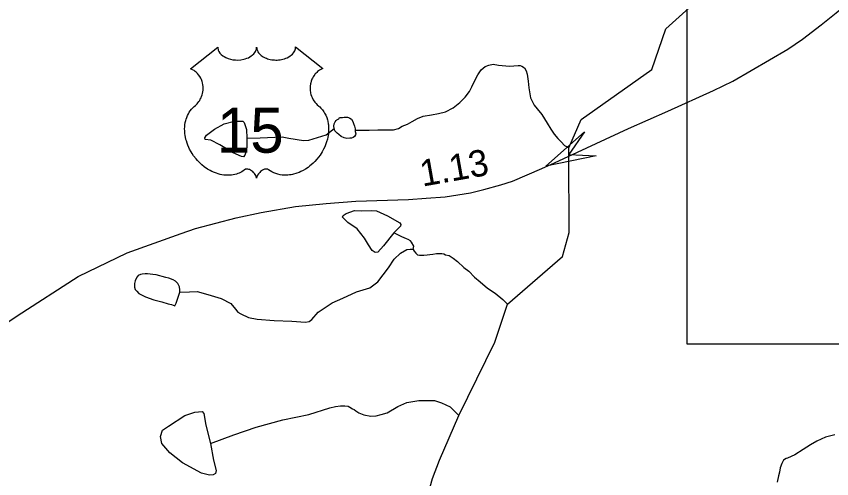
# Model space of a CAD drawing. Extents: x 2056842 to 2160602, y 826753 to 1016856.
# Drawn here: x 2083491 to 2087342, y 858683 to 860868 of the extents above; entities that cross this region are included whole.
import ezdxf

# ---------------------------------------------------------------- set-up
doc = ezdxf.new("R2010")
doc.units = 0
for name, color, linetype in [('Exist Hydrographic Creek Single Shore', 7, 'Continuous'), ('Exist Hydrographic Misc Water Feature', 7, 'Continuous'), ('Exist Road Primary US Attributed', 7, 'Continuous'), ('Exist Road Primary US Mileage Hundredths English Label', 7, 'Continuous'), ('Exist Road Primary US Shield CELL', 7, 'Continuous'), ('Exist Road Primary US Shield Number Label', 7, 'Continuous'), ('Exist Road Secondary Structure Standard Bridge Attributed CELL', 7, 'Continuous'), ('Scratch_Level_6', 7, 'Continuous')]:
    doc.layers.add(name, color=color, linetype=linetype)

msp = doc.modelspace()

# ---------------------------------------------------------------- linework, layer by layer
at = {"layer": 'Exist Hydrographic Creek Single Shore'}
for points in [[(2085430.2, 858588.1), (2085456.5, 858684.3), (2085489.3, 858770.4), (2085580.3, 858981.4), (2085750.8, 859329), (2085810.3, 859508.3), (2086070.2, 859732.9), (2086102.2, 859847.1), (2086100.6, 860214.6), (2086101.3, 860247.4), (2086159.2, 860380.8), (2086492.2, 860616.7), (2086558.2, 860809), (2086732.3, 860966.2)], [(2087356.4, 858890.9), (2087312.3, 858879), (2087272.3, 858860.7), (2087242.4, 858842.5), (2087206.5, 858820.7), (2087168.6, 858796.5), (2087132.7, 858780.4), (2087126.3, 858778.5), (2087114.8, 858770.1), (2087106.6, 858754.3), (2087098.6, 858734.4), (2087094.9, 858714.3), (2087091.1, 858696.2), (2087084.7, 858666.3)]]:
    msp.add_lwpolyline(points, dxfattribs=at)
at = {"layer": 'Exist Hydrographic Misc Water Feature'}
for points in [[(2085092.2, 860329.7), (2085099.8, 860329.7), (2085130.1, 860330.1), (2085158, 860329.8), (2085198, 860331.9), (2085223.8, 860332), (2085254.2, 860332.3), (2085272, 860332.5), (2085295.8, 860338.2), (2085313.7, 860348.5), (2085337.9, 860358.6), (2085360, 860370.7), (2085385.6, 860384.6), (2085411.9, 860396.9), (2085452.1, 860403), (2085485.7, 860409.2), (2085518.1, 860416.9), (2085553.8, 860435), (2085585.4, 860461.5), (2085611.6, 860485.5), (2085631.5, 860513.4), (2085643.2, 860535.5), (2085657.5, 860567.4), (2085671.3, 860591.7), (2085687.1, 860615.7), (2085705.1, 860631.6), (2085723.1, 860637.7), (2085742.8, 860641.7), (2085769.1, 860637.7), (2085785.3, 860635.7), (2085803.1, 860633.7), (2085821.2, 860631.9), (2085841.1, 860634.1), (2085860.9, 860636), (2085871.2, 860636), (2085879, 860632), (2085891.3, 860624.1), (2085899.1, 860610.3), (2085903.2, 860594.3), (2085909.3, 860562.1), (2085911.4, 860530.2), (2085919.4, 860482.2), (2085937.6, 860448.3), (2085951.6, 860430.3), (2085973.7, 860404.6), (2085997.7, 860362.9), (2086016, 860334.6), (2086032, 860310.6), (2086048.2, 860290.7), (2086064.4, 860274.9), (2086079.9, 860257.1), (2086101.3, 860247.4)], [(2084579.3, 860292.8), (2084580.6, 860254.5), (2084578, 860236.1), (2084570.1, 860212.3), (2084563.5, 860204.4), (2084554.3, 860205.8), (2084516.1, 860222.9), (2084452.9, 860261.1), (2084409.4, 860282.2), (2084383, 860286.2), (2084381.7, 860294.1), (2084389.6, 860307.3), (2084426.5, 860334.9), (2084472.6, 860360), (2084521.4, 860373.2), (2084560.9, 860373.2), (2084567.5, 860366.6), (2084578, 860333.6), (2084579.3, 860292.8)], [(2084992.3, 860337.5), (2084990.1, 860349.2), (2084992.1, 860359.5), (2084997.7, 860369.6), (2085002, 860375.4), (2085005.7, 860379.4), (2085014.1, 860383.8), (2085018, 860389.6), (2085032.1, 860389.5), (2085040.1, 860391.6), (2085045.9, 860391.5), (2085055.7, 860391.7), (2085060.2, 860389.7), (2085066.2, 860387.6), (2085074, 860381.5), (2085080.1, 860371.7), (2085084, 860361.8), (2085088.3, 860349.7), (2085092, 860335.8), (2085092.2, 860329.7)], [(2084579.3, 860292.8), (2084642.6, 860294.1), (2084746.7, 860298), (2084778.3, 860292.8), (2084848.1, 860280.9), (2084873.1, 860283.5), (2084954.8, 860308.6), (2084992.3, 860337.5)], [(2085092.2, 860329.7), (2085092, 860323.6), (2085094.3, 860313.5), (2085092.4, 860307.8), (2085088.5, 860299.8), (2085082.2, 860295.5), (2085074, 860291.9), (2085066.4, 860291.8), (2085052.2, 860291.5), (2085040.3, 860293.3), (2085026, 860299.6), (2085014.5, 860309.4), (2085006.1, 860315.6), (2084996.2, 860327.6), (2084992.3, 860337.5)], [(2085273.5, 859844.5), (2085225.8, 859783.1), (2085198.1, 859754.1), (2085186.3, 859752.8), (2085171.8, 859760.7), (2085154.7, 859788.4), (2085134.9, 859820), (2085100.7, 859863.5), (2085057.2, 859893.9), (2085032.1, 859918.9), (2085034.8, 859926.8), (2085049.3, 859936), (2085088.8, 859950.5), (2085123.1, 859949.2), (2085166.5, 859950.5), (2085191.6, 859949.2), (2085244.3, 859925.5), (2085302.2, 859892.5), (2085307.5, 859884.6), (2085304.9, 859876.7), (2085273.5, 859844.5)], [(2085365.5, 859766.8), (2085367.8, 859782.7), (2085357.5, 859800.5), (2085353.6, 859806.8), (2085341.8, 859812.7), (2085334, 859816.7), (2085311.8, 859826.5), (2085289.7, 859836.4), (2085273.5, 859844.5)], [(2084263.9, 859564.5), (2084309.2, 859566.9), (2084344.8, 859568.2), (2084396.2, 859553.7), (2084459.4, 859534), (2084504.2, 859510.2), (2084526.6, 859483.9), (2084537.4, 859470.7), (2084551.9, 859462.8), (2084587.5, 859444.3), (2084628.3, 859437.7), (2084708.7, 859431.1), (2084791.7, 859427.2), (2084856.3, 859423.2), (2084874.7, 859425.9), (2084886.6, 859435.1), (2084916.9, 859469.4), (2084983.4, 859514.2), (2085033.5, 859536.6), (2085098, 859565.6), (2085161.3, 859585.4), (2085198.1, 859613.1), (2085249.5, 859679), (2085275.9, 859719.8), (2085304.9, 859748.8), (2085335.8, 859766.5), (2085351.8, 859768.5), (2085360, 859768.5), (2085365.5, 859766.8)], [(2085365.5, 859766.8), (2085369.8, 859758.9), (2085377.8, 859748.8), (2085385.8, 859740.6), (2085395.7, 859738.7), (2085415.8, 859738.9), (2085431.8, 859741), (2085444.1, 859742.8), (2085458, 859744.7), (2085475.7, 859746.9), (2085485.9, 859747), (2085500.1, 859746.9), (2085509.9, 859745), (2085517.7, 859741.3), (2085535.7, 859737.4), (2085554.2, 859725.3), (2085574.1, 859709.3), (2085604.2, 859681.6), (2085628, 859663.4), (2085654.3, 859635.4), (2085682.1, 859613.8), (2085716.4, 859583.9), (2085752.3, 859559.7), (2085788.6, 859529.9), (2085806.8, 859512.1), (2085810.3, 859508.3)], [(2084263.9, 859564.5), (2084263.7, 859576.3), (2084261.9, 859590.3), (2084253.9, 859606.2), (2084243.6, 859616.2), (2084231.3, 859622.2), (2084211.4, 859630), (2084197.7, 859634.2), (2084151.5, 859646), (2084135.3, 859648.1), (2084123.4, 859649.9), (2084111.3, 859651.7), (2084099.5, 859651.9), (2084085.5, 859650), (2084077.5, 859647.9), (2084067.5, 859643.8), (2084061.5, 859637.8), (2084055.6, 859625.7), (2084053.3, 859617.5), (2084049.6, 859605.5), (2084049.6, 859587.6), (2084051.9, 859577.5), (2084059.9, 859569.8), (2084069.7, 859557.8), (2084101.9, 859542), (2084140.1, 859528.1), (2084178, 859518.3), (2084207.9, 859510.1), (2084223.9, 859506.4), (2084239.9, 859500.3), (2084246.3, 859512.4), (2084260, 859554.5), (2084263.9, 859564.5)], [(2084408.5, 858849.5), (2084517.8, 858890.4), (2084623.2, 858926), (2084749.7, 858961.6), (2084872.2, 858986.6), (2084972.2, 859017.4), (2084998.3, 859023.6), (2085021.9, 859027.7), (2085042.4, 859027.9), (2085058.2, 859025.9), (2085066, 859021.8), (2085078.3, 859013.9), (2085086.1, 859009.9), (2085094, 859003.8), (2085108.2, 858993.9), (2085132.4, 858984.2), (2085166.2, 858978.2), (2085190.4, 858980.2), (2085214.4, 858986.4), (2085242.5, 858994.3), (2085292.7, 859024.9), (2085336.2, 859043.3), (2085392.9, 859052.5), (2085465.7, 859052.5), (2085498.7, 859042), (2085539.5, 859022.2), (2085580.3, 858981.4)], [(2084408.5, 858849.5), (2084422.9, 858770.4), (2084434.8, 858721.7), (2084432.2, 858707.2), (2084421.6, 858700.6), (2084403.2, 858699.2), (2084366.3, 858708.5), (2084276.7, 858757.2), (2084216.1, 858804.7), (2084177.9, 858849.5), (2084172.6, 858882.5), (2084181.8, 858912.8), (2084209.5, 858931.3), (2084287.2, 858981.4), (2084334.7, 858997.2), (2084368.9, 859001.1), (2084376.8, 858991.9), (2084386.1, 858935.2), (2084408.5, 858849.5)]]:
    msp.add_lwpolyline(points, dxfattribs=at)
at = {"layer": 'Exist Road Primary US Attributed'}
for points in [[(2086033, 860176.3), (2086382.7, 860337.4), (2086568.5, 860419.7), (2086783.9, 860517.6), (2086874.6, 860562.4), (2087134.2, 860713.4), (2087203.6, 860761), (2087292.5, 860827.6), (2087363.6, 860884.7), (2087421.8, 860931.7), (2087522.6, 861021.9), (2087580.2, 861073.2), (2087655, 861156.5), (2087756.4, 861257.9), (2087847.1, 861353.6), (2088051.8, 861569.5), (2088101.6, 861623.8), (2088246.5, 861762), (2088336.6, 861840.3), (2088389.1, 861879.1)], [(2083204.4, 859259.1), (2083321.4, 859337.5), (2083495.9, 859453.3), (2083784.1, 859638.7), (2084014.7, 859751), (2084269.8, 859842.2), (2084337.5, 859865.1), (2084529.4, 859916.6), (2084647, 859941.2), (2084809.8, 859968.7), (2084954.7, 859984.3), (2085095.2, 859994.4), (2085343, 860002.8), (2085426.4, 860009), (2085517.1, 860015.7), (2085635.7, 860034.7), (2085698.4, 860049.8), (2085778.9, 860071.6), (2085833.8, 860089), (2085973.1, 860148.3), (2086033, 860176.3)]]:
    msp.add_lwpolyline(points, dxfattribs=at)
at = {"layer": 'Exist Road Primary US Shield CELL'}
msp.add_lwpolyline([(2084442.2, 860723), (2084442.5, 860717.6), (2084443.8, 860711.3), (2084444.8, 860708.1), (2084447.8, 860701.8), (2084452.6, 860694.5), (2084459.4, 860687.2), (2084467.1, 860680.9), (2084472.3, 860677.6), (2084481, 860672.9), (2084491, 860668.7), (2084502.1, 860665.5), (2084513.4, 860663.2), (2084525.8, 860661.9), (2084538, 860661.6), (2084551.2, 860662.6), (2084565.8, 860665.4), (2084572.6, 860667.2), (2084580.1, 860669.8), (2084587.1, 860672.7), (2084594.7, 860676.8), (2084600.9, 860680.7), (2084605.7, 860684.2), (2084612.5, 860690.7), (2084618, 860697.5), (2084620.2, 860701.3), (2084622.2, 860704.9), (2084624.9, 860712.7), (2084625.7, 860716.1), (2084626.2, 860723.2), (2084626.7, 860717.3), (2084627.3, 860713.5), (2084628.3, 860709.9), (2084629.8, 860706), (2084632.5, 860700.5), (2084635.5, 860696), (2084641.3, 860689.2), (2084644.9, 860685.9), (2084648.1, 860683.2), (2084656.9, 860677.2), (2084667.1, 860672), (2084672.1, 860669.8), (2084677.2, 860668), (2084683.8, 860666), (2084690.5, 860664.4), (2084697.2, 860663.3), (2084704.1, 860662.3), (2084711, 860661.8), (2084716.7, 860661.6), (2084723.7, 860661.7), (2084730.2, 860662.1), (2084736.8, 860662.8), (2084744.1, 860664.1), (2084749.9, 860665.4), (2084757.7, 860667.4), (2084764.7, 860669.9), (2084770.8, 860672.6), (2084778.8, 860676.8), (2084785.2, 860680.8), (2084790, 860684.6), (2084795.6, 860689.7), (2084800.9, 860695.9), (2084804, 860700.4), (2084806.2, 860705), (2084808.3, 860709.9), (2084809.5, 860715.1), (2084810.1, 860719.5), (2084810.2, 860723.4), (2084938.8, 860620.9), (2084935.8, 860619.8), (2084928.8, 860616.3), (2084923.3, 860613.1), (2084914.4, 860606.8), (2084910.6, 860603.4), (2084906.8, 860599.9), (2084903.3, 860596.1), (2084900.3, 860592.5), (2084896.5, 860587.3), (2084893.2, 860582.1), (2084889.9, 860576.4), (2084887.5, 860571.5), (2084883.6, 860561.2), (2084881.7, 860554.6), (2084880.5, 860549.1), (2084879, 860537.6), (2084878.6, 860532.2), (2084878.6, 860526.8), (2084878.9, 860521.1), (2084879.4, 860515.6), (2084880.4, 860509.9), (2084881.3, 860504.9), (2084882.9, 860498.7), (2084885.2, 860491.6), (2084888, 860484.7), (2084893.9, 860473.5), (2084901.4, 860462.1), (2084906.8, 860455.7), (2084912.1, 860450.2), (2084920.1, 860443.6), (2084924.4, 860439.8), (2084929.3, 860434.8), (2084937.4, 860425.5), (2084940.6, 860421.1), (2084943.9, 860416.1), (2084947, 860411), (2084950, 860405.6), (2084952.4, 860400.8), (2084957, 860389.8), (2084960.3, 860379), (2084961.8, 860373.4), (2084964.2, 860360.8), (2084965.1, 860354.6), (2084966.1, 860342.3), (2084966.1, 860327.4), (2084965, 860313.2), (2084962.3, 860296.7), (2084960.1, 860286.9), (2084956.7, 860275.4), (2084953.5, 860265.4), (2084947.6, 860250.8), (2084942.4, 860240.1), (2084935.6, 860227.7), (2084931, 860220.1), (2084925.6, 860212.1), (2084918.8, 860202.8), (2084910.9, 860192.9), (2084901.4, 860182.5), (2084893.8, 860174.9), (2084883.7, 860165.9), (2084877.7, 860160.9), (2084869, 860154.3), (2084857.2, 860146.4), (2084845.5, 860139.7), (2084835.5, 860134.6), (2084826.7, 860130.8), (2084815.3, 860126.5), (2084796.3, 860121.2), (2084789.4, 860119.8), (2084781.2, 860118.6), (2084773.5, 860117.8), (2084766.1, 860117.3), (2084756.1, 860117.3), (2084746.1, 860118.1), (2084736.7, 860119.5), (2084726.9, 860121.5), (2084716.7, 860124.6), (2084707.4, 860128.2), (2084697.9, 860132.8), (2084682, 860142.9), (2084677.4, 860145.3), (2084674.9, 860146), (2084668.7, 860146.3), (2084662.9, 860145.1), (2084657, 860142.7), (2084653.4, 860140.8), (2084648.7, 860137.7), (2084645, 860134.8), (2084640.6, 860130.6), (2084637.6, 860127.1), (2084635.3, 860124.4), (2084630.8, 860117.3), (2084629.2, 860114), (2084627.5, 860109.7), (2084626.1, 860103.3), (2084624, 860111.3), (2084621.7, 860116.7), (2084619, 860121.2), (2084616.1, 860125.2), (2084611.6, 860130.4), (2084607.6, 860134.3), (2084602.7, 860138.2), (2084597.6, 860141.3), (2084593.4, 860143.5), (2084589.6, 860144.9), (2084585, 860146.1), (2084581.2, 860146.4), (2084578.1, 860146.3), (2084573.8, 860145.3), (2084568, 860141.1), (2084562.5, 860137.3), (2084556.5, 860133.6), (2084549.3, 860129.8), (2084544.1, 860127.4), (2084537.9, 860124.9), (2084530.6, 860122.5), (2084522.7, 860120.5), (2084514.6, 860118.9), (2084507.4, 860117.7), (2084499.8, 860117), (2084492.8, 860116.8), (2084485.6, 860116.9), (2084478.9, 860117.4), (2084471, 860118.1), (2084461.3, 860119.5), (2084453.3, 860121.4), (2084444.8, 860123.6), (2084436, 860126.4), (2084426.7, 860130), (2084415, 860135), (2084406.9, 860139.2), (2084394, 860146.6), (2084379, 860157), (2084367.6, 860166.2), (2084359.3, 860173.7), (2084347.1, 860186.2), (2084339.9, 860194.3), (2084328.6, 860208.9), (2084321.4, 860219.5), (2084316.8, 860227.2), (2084309.9, 860239.7), (2084306.2, 860247.5), (2084301.3, 860258.9), (2084297.5, 860269.3), (2084294.3, 860279.2), (2084292.6, 860285.5), (2084290.1, 860296.5), (2084288.7, 860304.3), (2084287.2, 860315.1), (2084286.4, 860326.4), (2084286.3, 860336.8), (2084286.5, 860345.4), (2084287.5, 860355.6), (2084289.2, 860366.3), (2084291.3, 860375.5), (2084293.1, 860382.1), (2084295.9, 860390.1), (2084299.5, 860399), (2084303.7, 860407.5), (2084307.8, 860414.6), (2084312.9, 860422.2), (2084317.9, 860428.7), (2084324.5, 860435.8), (2084331.3, 860442.3), (2084337.6, 860447.4), (2084345, 860454.7), (2084348.9, 860459.1), (2084353.6, 860465.3), (2084357.3, 860471), (2084360.2, 860476.1), (2084364.2, 860483.6), (2084366.5, 860489.2), (2084369.5, 860497.9), (2084371, 860504), (2084372.5, 860511.8), (2084373.5, 860519.2), (2084373.8, 860528.4), (2084373.6, 860535.9), (2084372.6, 860544.8), (2084371, 860553.3), (2084368.9, 860560.8), (2084365.8, 860569.3), (2084362.8, 860575.5), (2084357.9, 860584), (2084352.4, 860591.8), (2084346.8, 860598.2), (2084341.1, 860603.9), (2084335.6, 860608.1), (2084330.4, 860611.9), (2084323.9, 860615.8), (2084317.6, 860618.9), (2084313.6, 860620.5)], close=True, dxfattribs=at)
at = {"layer": 'Exist Road Secondary Structure Standard Bridge Attributed CELL'}
msp.add_lwpolyline([(2086230.4, 860208.6), (2085991.4, 860160.4), (2086174.3, 860321.7), (2086100.6, 860214.6)], close=True, dxfattribs=at)
at = {"layer": 'Scratch_Level_6'}
msp.add_lwpolyline([(2086659.3, 866617.9), (2097771.9, 866617.9), (2097771.9, 859318.2), (2086659.3, 859318.2)], close=True, dxfattribs=at)

# ---------------------------------------------------------------- texts
at = {"layer": 'Exist Road Primary US Mileage Hundredths English Label'}
msp.add_text('1.13', height=125, rotation=10.0673, dxfattribs=at).set_placement((2085409.1, 860063.1))
at = {"layer": 'Exist Road Primary US Shield Number Label'}
msp.add_text('15', height=212.5, dxfattribs=at).set_placement((2084437.9, 860223.7))

doc.saveas('drawing.dxf')
